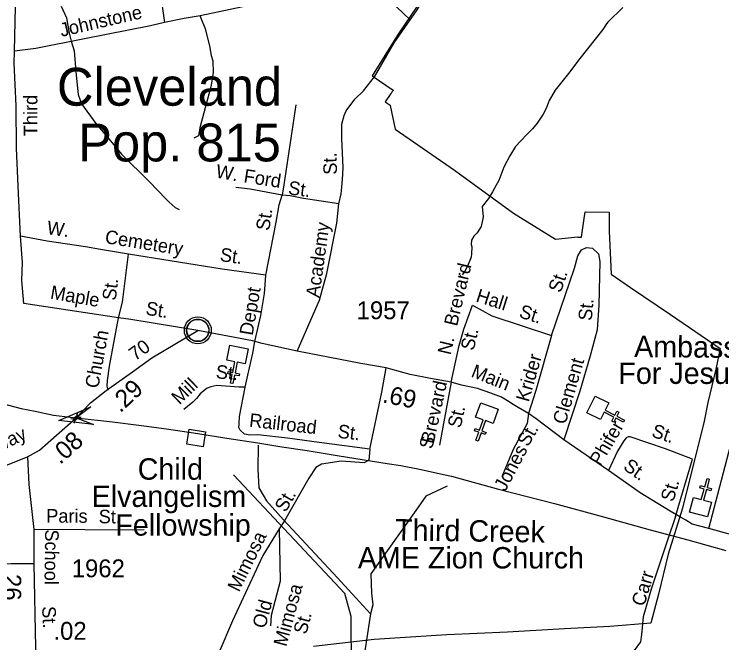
# Model space of a CAD drawing. Extents: x 1473865 to 1648260, y 639067 to 773536.
# Drawn here: x 1500653 to 1505606, y 723998 to 728401 of the extents above; entities that cross this region are included whole.
import ezdxf

# ---------------------------------------------------------------- set-up
doc = ezdxf.new("R2010")
doc.units = 0
for name, color, linetype in [('Exist Boundary Political City Limit New', 7, 'Continuous'), ('Exist Civil Demographics City Label', 7, 'Continuous'), ('Exist Civil Demographics Community CELL', 7, 'Continuous'), ('Exist Cultural Church CELL', 7, 'Continuous'), ('Exist Cultural Church Label', 7, 'Continuous'), ('Exist Hydrographic Creek Single Shore', 7, 'Continuous'), ('Exist Hydrographic Misc Water Feature', 7, 'Continuous'), ('Exist Railroad Mainline', 7, 'Continuous'), ('Exist Railroad Station CELL', 7, 'Continuous'), ('Exist Road Non-System Type 51', 7, 'Continuous'), ('Exist Road Non-System Type 51 Label', 7, 'Continuous'), ('Exist Road Secondary Mileage Hundredths English Label', 7, 'Continuous'), ('Exist Road Secondary Structure Standard Bridge Attributed CELL', 7, 'Continuous'), ('Exist Road Secondary Structure Standard Bridge CELL', 7, 'Continuous'), ('Exist Road Secondary Type 51 Attributed', 7, 'Continuous'), ('Exist Road Secondary Type 51 Label', 7, 'Continuous'), ('Exist Road Secondary Type 51 Number Label', 7, 'Continuous'), ('Map Preparation Boundary City Limit Buffer Line', 7, 'Continuous')]:
    doc.layers.add(name, color=color, linetype=linetype)

msp = doc.modelspace()

# ---------------------------------------------------------------- linework, layer by layer
at = {"layer": 'Exist Boundary Political City Limit New'}
msp.add_lwpolyline([(1503611.8, 728662.5), (1503336, 728253.7), (1503158.4, 727969.5), (1503306.1, 727868.4), (1503304.8, 727866.6), (1503299.2, 727858.4), (1503290.6, 727845.9), (1503289.5, 727844.2), (1503249.6, 727785.9), (1503283.5, 727762.7), (1503283.8, 727760.6), (1503285.5, 727761.3), (1503319.5, 727595.9), (1503734.4, 727308.9), (1504148.2, 727007.2), (1504442.4, 726825.8), (1504598, 726840.3), (1504599.1, 726839.6), (1504623.5, 726838.6), (1504640.8, 726952), (1504650.2, 727015.6), (1504816.8, 727014), (1504817, 726880.1), (1504830.4, 726580.5), (1504965.6, 726486), (1505246.5, 726296.9), (1505593.6, 726059.4), (1505563, 725913.8), (1505506.9, 725681.3), (1505481.4, 725551), (1505330.8, 724940.4), (1505231.1, 724618.6), (1505162.2, 724337.6), (1505108.6, 724135.8), (1504822.8, 724112.8), (1504503.6, 724094.9), (1504105.4, 724071.9), (1503681.6, 724054), (1503173.6, 724020.8), (1502748.2, 723972.8)], dxfattribs=at)
at = {"layer": 'Exist Civil Demographics Community CELL'}
msp.add_lwpolyline([(1501860.5, 726198.6), (1501861.5, 726204.2), (1501863.3, 726210.7), (1501866.2, 726217.9), (1501869.1, 726223.7), (1501872.5, 726229.4), (1501876.2, 726234.5), (1501880.2, 726238.9), (1501884.8, 726243.5), (1501890.3, 726248.1), (1501895.8, 726251.7), (1501900.6, 726254.6), (1501905.7, 726257.1), (1501911.2, 726259.4), (1501916.8, 726261.2), (1501921.1, 726262.3), (1501926, 726263.1), (1501930.1, 726263.8), (1501936.5, 726264.1), (1501940.9, 726264), (1501946.6, 726263.7), (1501951.5, 726263), (1501956.4, 726262), (1501961.4, 726260.6), (1501966.5, 726258.6), (1501973.2, 726255.7), (1501979.5, 726252.2), (1501984.5, 726248.7), (1501989.7, 726244.6), (1501993, 726241.5), (1501997.1, 726237.1), (1502001, 726232.4), (1502004.1, 726227.8), (1502007.2, 726222.8), (1502009.6, 726217.7), (1502011.7, 726212.7), (1502013.2, 726207.7), (1502014.5, 726203.1), (1502015.6, 726197), (1502016.2, 726192.3), (1502016.5, 726186.3), (1502016.3, 726180.5), (1502015.7, 726174.8), (1502014.8, 726169.4), (1502013.2, 726163.2), (1502011.3, 726157.4), (1502009, 726152.3), (1502005.8, 726146.3), (1502002.5, 726141), (1501999.1, 726136.3), (1501994.9, 726131.5), (1501989.6, 726126.6), (1501984.6, 726122.4), (1501979.6, 726119), (1501975.2, 726116.5), (1501968.4, 726113.3), (1501961.3, 726110.5), (1501955.3, 726109.1), (1501948.7, 726107.8), (1501944.3, 726107.3), (1501939.8, 726107.1), (1501934.2, 726107.1), (1501929.9, 726107.5), (1501924.3, 726108.2), (1501918.4, 726109.5), (1501913.8, 726110.8), (1501908.6, 726112.7), (1501904, 726114.7), (1501900.1, 726116.9), (1501893.3, 726121), (1501887.7, 726125.3), (1501882.8, 726129.7), (1501878.4, 726134.6), (1501875.2, 726138.6), (1501872.2, 726142.7), (1501868.1, 726149.8), (1501866.4, 726153.4), (1501864.7, 726157.4), (1501862.1, 726165.6), (1501860.5, 726172.6), (1501859.9, 726177.8), (1501859.5, 726184.1), (1501859.5, 726188.8), (1501860, 726195.3)], close=True, dxfattribs=at)
for centre, radius in [((1501938.2, 726186.1), 94.3), ((1501937.9, 726186.4), 76.7)]:
    msp.add_circle(centre, radius, dxfattribs=at)
at = {"layer": 'Exist Cultural Church CELL'}
for points in [[(1502269.4, 725952), (1502213.6, 725963.2), (1502198.6, 725888.5), (1502229.9, 725882.2), (1502226.8, 725866.6), (1502195.4, 725872.9), (1502183.5, 725813.9), (1502167.8, 725817.1), (1502179.7, 725876), (1502148.3, 725882.4), (1502151.5, 725898), (1502182.9, 725891.7), (1502197.9, 725966.3), (1502141.4, 725977.8), (1502162.4, 726082.2), (1502290.5, 726056.4)], [(1504814.8, 725677.5), (1504789.2, 725626.6), (1504857.1, 725592.2), (1504871.5, 725620.8), (1504885.8, 725613.5), (1504871.3, 725585), (1504925, 725557.8), (1504917.8, 725543.5), (1504864.1, 725570.7), (1504849.6, 725542.2), (1504835.4, 725549.4), (1504849.8, 725577.9), (1504781.9, 725612.3), (1504755.8, 725560.9), (1504660.8, 725609), (1504719.8, 725725.6)], [(1504005.1, 725534.7), (1503951.5, 725553.8), (1503925.7, 725482.2), (1503955.8, 725471.4), (1503950.4, 725456.3), (1503920.3, 725467.2), (1503899.9, 725410.6), (1503884.8, 725416), (1503905.2, 725472.6), (1503875.1, 725483.4), (1503880.5, 725498.5), (1503910.6, 725487.6), (1503936.4, 725559.3), (1503882.2, 725578.9), (1503918.2, 725679.1), (1504041.1, 725634.8)], [(1505407.4, 725016.5), (1505462.3, 725001.5), (1505482.5, 725074.9), (1505451.6, 725083.4), (1505455.8, 725098.8), (1505486.7, 725090.3), (1505502.6, 725148.3), (1505518.1, 725144.1), (1505502.1, 725086.1), (1505533, 725077.6), (1505528.8, 725062.2), (1505497.9, 725070.7), (1505477.7, 724997.3), (1505533.3, 724981.9), (1505505.1, 724879.2), (1505379.2, 724913.8)]]:
    msp.add_lwpolyline(points, close=True, dxfattribs=at)
at = {"layer": 'Exist Hydrographic Creek Single Shore'}
msp.add_lwpolyline([(1503722.2, 720919), (1503600.2, 721066), (1503500.2, 721123.8), (1503427.2, 721210.6), (1503303.3, 721285.3), (1503254.3, 721345.4), (1503206.2, 721454.7), (1503202.2, 721681.3), (1503147.2, 721872.7), (1503150.2, 722089.4), (1503176.2, 722138.1), (1503149.3, 722480), (1502894.2, 722718.2), (1502847.2, 722870.2), (1502858.2, 723070.1), (1503013.2, 723808.9), (1503011.3, 724183.2), (1502966.4, 724344.3), (1502188.4, 725174.1)], dxfattribs=at)
at = {"layer": 'Exist Hydrographic Misc Water Feature'}
for points in [[(1500981.4, 728456.1), (1501019.9, 728375.4), (1501038.6, 728268), (1501052.9, 728210.9), (1501071.8, 728142.6), (1501085.2, 727998.5), (1501091.9, 727926.3), (1501100.3, 727838.3), (1501124.8, 727772.5), (1501224.6, 727634), (1501314.8, 727526.4), (1501404.9, 727420.8), (1501599.5, 727225.2), (1501715.3, 727107.1), (1501737, 727082.8), (1501780.2, 727045.9), (1501808, 727031.4)], [(1504913.8, 728447.6), (1504807.9, 728343.7), (1504799.8, 728333.8), (1504773.1, 728292.4), (1504611.4, 728089.6), (1504533.6, 727985.1), (1504439.5, 727869), (1504398.1, 727795.8), (1504377.1, 727740.3), (1504356.4, 727700.7), (1504313.2, 727637.5), (1504280.5, 727598.2), (1504237.8, 727555), (1504162.6, 727473.5), (1504121.1, 727407.3), (1504079.7, 727328.2), (1504044, 727234.9), (1504027.5, 727203.3), (1504000.6, 727155.8), (1503973.8, 727108.3), (1503928.8, 727053.2), (1503935.5, 726981.1), (1503922.3, 726913.4), (1503893.5, 726868), (1503869, 726844.5), (1503852.6, 726818.8), (1503852, 726786.9), (1503855.8, 726770.8), (1503854.8, 726722.8), (1503850.4, 726698.9), (1503825.3, 726635.5), (1503804.6, 726595.9), (1503788.2, 726574.2)]]:
    msp.add_lwpolyline(points, dxfattribs=at)
at = {"layer": 'Exist Railroad Mainline'}
for points in [[(1500558.6, 725675.8), (1500701.9, 725639.7), (1500798.9, 725619.9), (1500929.1, 725591.5), (1501085.8, 725572.6), (1501340.7, 725546.1), (1501526.3, 725521.5), (1501717.9, 725496.6)], [(1501717.9, 725496.6), (1501937.6, 725463.6), (1502141, 725430.7), (1502358.5, 725397.5), (1502526, 725371.1), (1502704.4, 725344.5), (1502927.1, 725307.3), (1503264.2, 725254.3), (1503358.4, 725238.6), (1503490.3, 725212.9), (1503584.6, 725194), (1503658.9, 725177.7), (1503714.9, 725166), (1504043.6, 725073.1), (1504434, 724973.6), (1504776.7, 724880.6), (1505105.2, 724789.9), (1505368.3, 724718.2), (1505633.1, 724644.2)]]:
    msp.add_lwpolyline(points, dxfattribs=at)
at = {"layer": 'Exist Railroad Station CELL'}
msp.add_lwpolyline([(1501877.8, 725495), (1501992.9, 725476.3), (1501975.9, 725371.3), (1501860.8, 725389.9)], close=True, dxfattribs=at)
at = {"layer": 'Exist Road Non-System Type 51'}
for p, q in [((1502946, 728599.9), (1501954, 728387.8)), ((1505514.2, 724798.1), (1505706.4, 725529.2))]:
    msp.add_line(p, q, dxfattribs=at)
for points in [[(1501861.9, 729021.7), (1501718.1, 729001.1), (1501711.2, 728999.4), (1501694.7, 728993.3), (1501624.7, 728977), (1501596.8, 728935.1), (1501610.8, 728870.9), (1501638.7, 728750.8), (1501652.6, 728669.9), (1501666.6, 728588.9), (1501680.8, 728507.6), (1501704.1, 728342.2)], [(1503423.8, 728361), (1503469.8, 728424.4), (1503525.7, 728513.9), (1503590.3, 728609.7), (1503607.7, 728635.8), (1503617.7, 728659.4)], [(1503423.8, 728361), (1503284.6, 728494), (1503206.2, 728557.8), (1503180.2, 728571.1), (1503116.9, 728606), (1503063.2, 728599.9), (1502946, 728599.9)], [(1501954, 728387.8), (1501842.3, 728371.1), (1501704.1, 728342.2)], [(1501912.9, 727534.4), (1501945.3, 727551.7), (1501956.4, 727615.5), (1502033.1, 727904.3), (1502048.8, 727991.3), (1502046, 728072.3), (1502035, 728109), (1502023.7, 728167.3), (1501995.3, 728290.5), (1501954, 728387.8)], [(1501704.1, 728342.2), (1501607.8, 728317.9), (1501144.7, 728227.2), (1500805.6, 728160.8), (1500655.1, 728140.3)], [(1502925.1, 727071.3), (1502940.4, 727143), (1502945.1, 727189), (1502952, 727242.9), (1502955.5, 727324.8), (1502946.8, 727530.9), (1502946.4, 727629), (1502961.4, 727690.7), (1502975.9, 727724.4), (1503037.4, 727805.4), (1503098.2, 727864.2), (1503173.8, 727961), (1503311.7, 728198.7), (1503423.8, 728361)], [(1502624.8, 727764.3), (1502541.4, 727205.7), (1502528.2, 727133.9)], [(1502528.2, 727133.9), (1502305.1, 727173.9), (1502205.3, 727187.5)], [(1502413.9, 726573.2), (1502485.7, 726944.8), (1502507.8, 727064.4), (1502528.2, 727133.9)], [(1502925.1, 727071.3), (1502677.8, 727109.5), (1502584.1, 727127), (1502528.2, 727133.9)], [(1502634, 726040.4), (1502789.5, 726397.3), (1502811.8, 726475.4), (1502841.5, 726583.3), (1502911, 726937.5), (1502925.1, 727071.3)], [(1501453.7, 726720.2), (1501258.2, 726751.6), (1501152.6, 726771.3), (1500883.2, 726809.8), (1500697.4, 726846.1)], [(1504413.1, 726149.9), (1504575.3, 726621.1), (1504597.7, 726708.6), (1504622.7, 726751), (1504657.7, 726766), (1504700.1, 726761), (1504742.5, 726721.1), (1504752.5, 726668.6), (1504745, 726361.3), (1504732.6, 726188.9), (1504685.1, 726006.5), (1504612.8, 725760.7), (1504500.4, 725418.4)], [(1501383.4, 726274), (1501412.1, 726382.9), (1501453.7, 726720.2)], [(1502413.9, 726573.2), (1502107.7, 726615.2), (1501453.7, 726720.2)], [(1502338.1, 726107), (1502378.3, 726290.6), (1502403.8, 726445), (1502408.8, 726505.3), (1502413.9, 726573.2)], [(1503711.6, 725822.7), (1503766.6, 726080), (1503799, 726194.9), (1503861.4, 726362.3)], [(1503861.4, 726362.3), (1503996.2, 726287.3), (1504200.9, 726219.9), (1504413.1, 726149.9)], [(1501309.8, 725766.8), (1501304.3, 725794.9), (1501306.9, 725834.9), (1501320.6, 725934.5), (1501383.4, 726274)], [(1504413.1, 726149.9), (1504303.3, 725765.2), (1504253.4, 725602.8)], [(1502269.4, 725788.2), (1502287.9, 725871.4), (1502323.4, 726026.5), (1502338.1, 726107)], [(1503141.9, 725353.2), (1503225.2, 725752.6), (1503255.4, 725923.7)], [(1502269.4, 725788.2), (1502225.4, 725788.9), (1502072.2, 725799.8), (1502030, 725790.7), (1502004, 725781), (1501981.7, 725765.5), (1501955.4, 725742), (1501928.7, 725708.3), (1501902.4, 725682.8), (1501839.5, 725631.8)], [(1503711.6, 725822.7), (1503629.2, 725383)], [(1503141.9, 725353.2), (1502787.5, 725400), (1502566, 725431.7), (1502358.4, 725455.1), (1502305.5, 725451.4), (1502265.3, 725459), (1502235.1, 725486.6), (1502225.1, 725506.8), (1502227.6, 725531.9), (1502230.1, 725582.2), (1502269.4, 725788.2)], [(1504253.4, 725602.8), (1504243.4, 725532.9), (1504146, 725350.5), (1504066.5, 725159.5)], [(1505281.4, 724883.2), (1505400.9, 725283.4), (1505212.3, 725357.1), (1504963.6, 725439.3), (1504951.6, 725439.6), (1504935.7, 725433.7), (1504919.3, 725412), (1504876.2, 725338.8), (1504812, 725203.9)], [(1502361, 725382), (1502358.5, 725213.5), (1502366, 725082.7), (1502418.8, 724992.1), (1502536.9, 724858.8), (1502916.4, 724453.9), (1503147.4, 724201.1)], [(1503141.9, 725353.2), (1503135, 725276.4), (1503102.3, 725258.8), (1502941.5, 725268.8), (1502803.3, 725248.7), (1502763.1, 725226.1), (1502715.3, 725150.6), (1502544.4, 724851.3)], [(1503682.7, 725095.6), (1503534.5, 725025.2), (1503464.1, 724924.6), (1503149.9, 724481.9), (1503155, 724346.1), (1503162.5, 724263.1), (1503147.4, 724201.1)], [(1502544.4, 724851.3), (1502506.8, 724796.8)], [(1505281.4, 724883.2), (1505226.9, 724722.5), (1505113, 724380.4), (1505056, 724179.1), (1505042.6, 724055), (1505035.9, 724004.7), (1504992.3, 723944.3), (1504928.6, 723900.7), (1504881.7, 723813.5), (1504891.7, 723716.2), (1504878.3, 723602.1), (1504844.8, 723461.2)], [(1501561.6, 724788.6), (1501503.5, 724785.6), (1500789.8, 724791.6)], [(1502506.8, 724796.8), (1502394.1, 724608.3), (1502180.5, 724150.6), (1502085.2, 723928.2), (1502024.9, 723762.2), (1501944.4, 723450.3)], [(1502506.8, 724796.8), (1502514.3, 724429.6), (1502451.5, 724188.1), (1502446.5, 724117.7)], [(1500790.1, 724549.9), (1500632.1, 724550.2), (1500556.1, 724545.4), (1500475.8, 724532.6), (1500293.2, 724485.4), (1500137.7, 724440.7)], [(1503147.4, 724201.1), (1503091.9, 723834.2), (1503041.7, 723605.4), (1502994.1, 723375.2), (1502986.5, 723279.6), (1502994.1, 723219.3), (1503049.3, 723174), (1503122.2, 723136.3), (1503190.1, 723131.2)]]:
    msp.add_lwpolyline(points, dxfattribs=at)
at = {"layer": 'Exist Road Secondary Structure Standard Bridge Attributed CELL'}
msp.add_lwpolyline([(1501207.4, 725526.7), (1500965.2, 725554.9), (1501189.1, 725651.5), (1501085.8, 725572.6)], close=True, dxfattribs=at)
at = {"layer": 'Exist Road Secondary Structure Standard Bridge CELL'}
for p, q in [((1501094, 725591.7), (1501095.1, 725608.9)), ((1501048.3, 725568), (1501065.5, 725566.8)), ((1501076, 725536.3), (1501077.1, 725553.5)), ((1501105.4, 725578.7), (1501122.6, 725577.5))]:
    msp.add_line(p, q, dxfattribs=at)
msp.add_lwpolyline([(1501065.5, 725566.8), (1501093.9, 725591.7), (1501105.6, 725578.4), (1501077.1, 725553.5)], close=True, dxfattribs=at)
at = {"layer": 'Exist Road Secondary Type 51 Attributed'}
for points in [[(1501938.2, 726186.1), (1501469.3, 726262.9), (1501383.4, 726274), (1500720.3, 726374.7), (1500707.2, 726535.5), (1500710.5, 726660.2), (1500697.4, 726846.1), (1500680.1, 727195.9), (1500669.8, 727463.1), (1500665.8, 727758.6), (1500654, 728056.3), (1500655.1, 728140.3), (1500661.3, 728451.2), (1500682.4, 728741.1), (1500687.8, 728851.1), (1500693.1, 728941.6), (1500712.8, 729311.6), (1500734.3, 729516.6), (1500739.8, 729620.1), (1500772.6, 729751.4), (1500889.6, 729989.1)], [(1501085.8, 725572.6), (1501186.3, 725677.5), (1501296.5, 725764.1), (1501481.9, 725895.8), (1501617.5, 725993.5), (1501938.2, 726186.1)], [(1506004.3, 724663.1), (1505514.2, 724798.1), (1505398.6, 724829.8), (1505354.5, 724856.2), (1505317.4, 724878.5), (1505243.1, 724919.4), (1505033.8, 725048.7), (1504812, 725203.9), (1504500.4, 725418.4), (1504305.8, 725565.3), (1504253.4, 725602.8), (1504181, 725645.3), (1504146, 725667.8), (1504106.1, 725692.7), (1504063.6, 725717.7), (1503988, 725745.3), (1503895.1, 725778.7), (1503784.4, 725802.3), (1503711.6, 725822.7), (1503567.2, 725849.3), (1503425.5, 725877.3), (1503290.1, 725913.6), (1503255.4, 725923.7), (1503079, 725953.3), (1502634, 726040.4), (1502387.7, 726094.7), (1502320, 726111.5), (1501938.2, 726186.1)], [(1500746, 725300.6), (1500831.1, 725346.8), (1501085.8, 725572.6)], [(1498915.5, 724476.9), (1498933.7, 724500), (1498961.7, 724543.7), (1498998.2, 724566.8), (1499225.6, 724647.1), (1499405.5, 724714), (1499634.4, 724819.1), (1499958.8, 724957.6), (1500043.2, 724990.2), (1500476.3, 725178.9), (1500587.4, 725236.3), (1500746, 725300.6)], [(1500746, 725300.6), (1500755.4, 725105.9), (1500789.8, 724791.6), (1500790.1, 724549.9), (1500801.2, 723961.6), (1500809.1, 723831.6)]]:
    msp.add_lwpolyline(points, dxfattribs=at)
at = {"layer": 'Map Preparation Boundary City Limit Buffer Line'}
msp.add_lwpolyline([(1503611.8, 728662.5), (1503336, 728253.7), (1503158.4, 727969.5), (1503306.1, 727868.4), (1503304.8, 727866.6), (1503299.2, 727858.4), (1503290.6, 727845.9), (1503289.5, 727844.2), (1503249.6, 727785.9), (1503283.5, 727762.7), (1503283.8, 727760.6), (1503285.5, 727761.3), (1503319.5, 727595.9), (1503734.4, 727308.9), (1504148.2, 727007.2), (1504442.4, 726825.8), (1504598, 726840.3), (1504599.1, 726839.6), (1504623.5, 726838.6), (1504640.8, 726952), (1504650.2, 727015.6), (1504816.8, 727014), (1504817, 726880.1), (1504830.4, 726580.5), (1504965.6, 726486), (1505246.5, 726296.9), (1505593.6, 726059.4), (1505563, 725913.8), (1505506.9, 725681.3), (1505481.4, 725551), (1505330.8, 724940.4), (1505231.1, 724618.6), (1505162.2, 724337.6), (1505108.6, 724135.8), (1504822.8, 724112.8), (1504503.6, 724094.9), (1504105.4, 724071.9), (1503681.6, 724054), (1503173.6, 724020.8), (1502748.2, 723972.8)], dxfattribs=at)

# ---------------------------------------------------------------- texts
at = {"layer": 'Exist Civil Demographics City Label'}
for s, p in [('Cleveland', (1500952.2, 727759.5)), ('Pop. 815', (1501100.8, 727369.2))]:
    msp.add_text(s, height=265, dxfattribs=at).set_placement(p)
at = {"layer": 'Exist Cultural Church Label'}
for s, rotation, p in [('Ambassador', 359.5103, (1504991.7, 725999.1)), ('For Jesus Christ', 0, (1504881.9, 725810.9)), ('Child ', 0, (1501517.4, 725140.1)), ('Elvangelism', 0, (1501195.3, 724949.3)), ('Fellowship', 0, (1501361.1, 724748.3)), ('Third Creek', 359.1726, (1503318.3, 724714.8)), ('AME Zion Church', 0, (1503058.2, 724518.3))]:
    msp.add_text(s, height=150, rotation=rotation, dxfattribs=at).set_placement(p)
at = {"layer": 'Exist Road Non-System Type 51 Label'}
for s, rotation, p in [('Johnstone', 13.0165, (1500983.9, 728240.6)), ('St.', 91.6044, (1502913.1, 727277.2)), ('W.', 349.8552, (1502059.5, 727256.9)), ('Ford', 351.219, (1502255.1, 727223.3)), ('St.', 352.2276, (1502566.4, 727139.3)), ('St.', 81.5173, (1502438.2, 726880.3)), ('W.', 351.8752, (1500877.9, 726860.2)), ('Academy', 82.0263, (1502787.7, 726411.6)), ('Cemetery', 350.875, (1501283.7, 726797.3)), ('St.', 351.5413, (1502088.6, 726672.2)), ('Brevard', 76.6913, (1503752.4, 726210.3)), ('St.', 70.8445, (1504477.8, 726444.3)), ('St.', 82.9647, (1501363.5, 726391.4)), ('Depot', 80.5046, (1502322.2, 726146)), ('Hall', 342.4211, (1503878.4, 726389.4)), ('St.', 84.9744, (1504695.4, 726250.6)), ('St.', 342.2238, (1504180.8, 726279)), ('Church', 79.5072, (1501241.1, 725775.5)), ('St.', 76.6913, (1503868.6, 726039.6)), ('N.', 76.6913, (1503707.2, 726009.3)), ('Krider', 74.1123, (1504254.2, 725679.4)), ('Clement', 73.6968, (1504511, 725521.7)), ('St.', 355.1376, (1502061.9, 725850.1)), ('Mill', 44.064, (1501809.4, 725661.3)), ('Brevard', 77.7479, (1503589.2, 725386.8)), ('Railroad', 353.5703, (1502294.6, 725511.8)), ('St.', 77.7479, (1503777.9, 725497.1)), ('Phifer', 59.5017, (1504755.3, 725230.6)), ('St.', 352.9875, (1502913.6, 725434.1)), ('St.', 59.9066, (1504248.7, 725365)), ('St.', 341.6956, (1505108, 725443.4)), ('S.', 77.7479, (1503579.2, 725350.2)), ('Jones', 61.9496, (1504090.1, 725053)), ('St.', 73.3693, (1505266.1, 724979.9)), ('St.', 59.9435, (1502552.5, 724906.1)), ('Paris', 359.5182, (1500877.1, 724840.1)), ('St.', 359.5182, (1501244.1, 724835)), ('Mimosa', 63.8328, (1502225.9, 724348.4)), ('Carr', 73.3693, (1505062.3, 724248.1)), ('Mimosa', 75.0117, (1502557.5, 723966.3)), ('Old', 75.0117, (1502410, 724093.3)), ('St.', 75.0117, (1502697, 724051.8))]:
    msp.add_text(s, height=95, rotation=rotation, dxfattribs=at).set_placement(p)
at = {"layer": 'Exist Road Secondary Mileage Hundredths English Label'}
for s, rotation, p in [('.29', 43.0605, (1501395.7, 725603.9)), ('.69', 348.8268, (1503225.5, 725682.6)), ('.08', 42.0592, (1500974.5, 725241.6)), ('.26', 270.077, (1500577.1, 724525.9)), ('.02', 0.0158, (1500927.8, 724019))]:
    msp.add_text(s, height=125, rotation=rotation, dxfattribs=at).set_placement(p)
at = {"layer": 'Exist Road Secondary Type 51 Label'}
for s, rotation, p in [('Third', 89.9342, (1500815, 727545.7)), ('Maple', 350.0274, (1500901, 726408.8)), ('St.', 350.7097, (1501568.7, 726296.4)), ('70', 35.7688, (1501499.3, 725969.1)), ('Main', 338.1741, (1503844.2, 725863.5)), ('Highway', 25.3025, (1500308.2, 725220.7)), ('St.', 325.0241, (1504909.2, 725217.6)), ('School', 269.318, (1500869.9, 724792.6)), ('St.', 272.3525, (1500848.2, 724252.7))]:
    msp.add_text(s, height=95, rotation=rotation, dxfattribs=at).set_placement(p)
at = {"layer": 'Exist Road Secondary Type 51 Number Label'}
for s, p in [('1957', (1503049.9, 726264.2)), ('1962', (1501055.8, 724456.9))]:
    msp.add_text(s, height=125, dxfattribs=at).set_placement(p)

doc.saveas('drawing.dxf')
